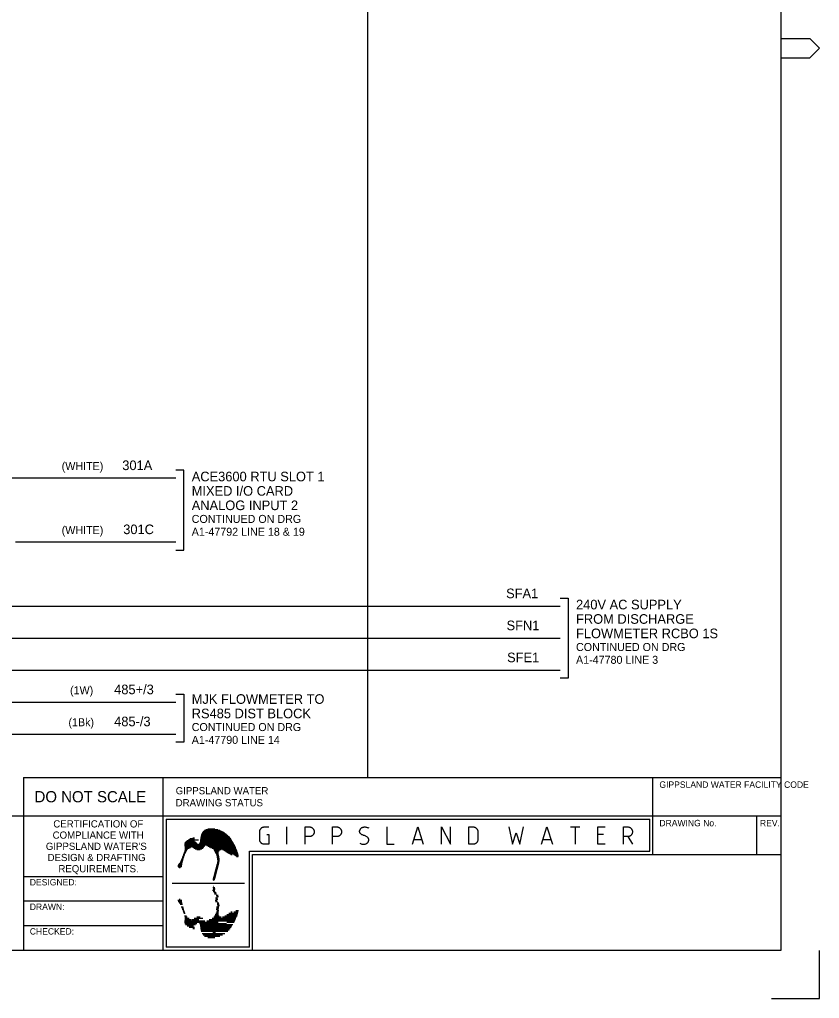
# Model space of a CAD drawing. Extents: x 0 to 841, y 0 to 594.
# Drawn here: x 591.2 to 841, y 0 to 305.7 of the extents above; entities that cross this region are included whole.
import ezdxf

# ---------------------------------------------------------------- set-up
doc = ezdxf.new("R2010")
doc.units = 0
doc.layers.add('A1BORDER', color=7, linetype='Continuous')
doc.layers.add('Level 1', color=7, linetype='Continuous')

msp = doc.modelspace()

# ---------------------------------------------------------------- linework, layer by layer
at = {"layer": 'A1BORDER'}
for p, q in [((829, 581), (829, 15)), ((829, 299.76), (838, 299.76)), ((838, 299.76), (841, 296.76)), ((838, 293.76), (841, 296.76)), ((829, 293.76), (838, 293.76)), ((592.5, 69), (592.5, 15)), ((592.5, 69), (829, 69)), ((636, 69), (636, 15)), ((789, 45), (789, 69)), ((28, 57), (829, 57)), ((637, 56), (788, 56)), ((637, 56), (637, 16)), ((788, 46), (788, 56)), ((821.5, 45), (821.5, 57)), ((648.53, 52.12), (654.64, 52.12)), ((648.74, 52.32), (654.24, 52.32)), ((649.02, 52.52), (653.76, 52.52)), ((649.39, 52.72), (653.15, 52.72)), ((650.01, 52.92), (652.2, 52.92)), ((643.04, 48.92), (646.16, 48.92)), ((643.26, 49.12), (645.9, 49.12)), ((643.54, 49.32), (645.57, 49.32)), ((643.85, 49.52), (647.09, 49.52)), ((644.18, 49.72), (645.89, 49.72)), ((644.54, 49.92), (645.36, 49.92)), ((645.37, 50.12), (645.86, 50.12)), ((647.61, 48.92), (657.8, 48.92)), ((647.63, 49.12), (657.68, 49.12)), ((647.66, 49.32), (657.57, 49.32)), ((647.69, 49.52), (657.44, 49.52)), ((647.71, 49.72), (657.31, 49.72)), ((647.75, 49.92), (657.17, 49.92)), ((647.78, 50.12), (657.02, 50.12)), ((647.81, 50.32), (656.86, 50.32)), ((647.85, 50.52), (656.69, 50.52)), ((647.88, 50.72), (656.5, 50.72)), ((647.91, 50.92), (656.3, 50.92)), ((647.96, 51.12), (656.08, 51.12)), ((648.03, 51.32), (655.85, 51.32)), ((648.12, 51.52), (655.59, 51.52)), ((648.23, 51.72), (655.31, 51.72)), ((648.37, 51.92), (655, 51.92)), ((642.72, 45.92), (643.3, 45.92)), ((642.73, 48.12), (658.25, 48.12)), ((642.74, 47.92), (658.35, 47.92)), ((642.75, 48.32), (646.79, 48.32)), ((642.79, 47.72), (649.08, 47.72)), ((642.79, 46.12), (643.4, 46.12)), ((642.81, 48.52), (646.55, 48.52)), ((642.83, 47.52), (648.95, 47.52)), ((642.84, 46.32), (643.5, 46.32)), ((642.85, 47.31), (644.88, 47.31)), ((642.87, 47.12), (644.57, 47.12)), ((642.87, 46.52), (643.6, 46.52)), ((642.88, 46.92), (644.23, 46.92)), ((642.88, 46.72), (643.83, 46.72)), ((642.9, 48.72), (646.37, 48.72)), ((645.14, 47.31), (648.83, 47.31)), ((645.49, 47.12), (648.67, 47.12)), ((645.76, 46.92), (648.42, 46.92)), ((646.05, 46.72), (648.11, 46.72)), ((646.62, 46.52), (647.67, 46.52)), ((647.19, 48.32), (658.14, 48.32)), ((647.42, 48.52), (658.03, 48.52)), ((647.54, 48.72), (657.92, 48.72)), ((649.72, 47.72), (658.45, 47.72)), ((650.12, 47.52), (658.55, 47.52)), ((650.48, 47.31), (658.64, 47.31)), ((650.87, 47.12), (658.73, 47.12)), ((651.36, 46.92), (658.82, 46.92)), ((651.76, 46.72), (658.9, 46.72)), ((651.88, 46.52), (654.15, 46.52)), ((651.99, 46.32), (653.71, 46.32)), ((652.1, 46.12), (653.52, 46.12)), ((652.2, 45.92), (653.4, 45.92)), ((654.57, 46.52), (658.99, 46.52)), ((655, 46.32), (659.07, 46.32)), ((655.31, 46.12), (659.14, 46.12)), ((655.62, 45.92), (659.22, 45.92)), ((663, 46), (788, 46)), ((663, 16), (663, 46)), ((641.55, 42.92), (642.2, 42.92)), ((641.64, 43.12), (642.25, 43.12)), ((641.73, 43.32), (642.3, 43.32)), ((641.82, 43.51), (642.35, 43.51)), ((641.91, 43.72), (642.41, 43.72)), ((641.99, 43.92), (642.48, 43.92)), ((642.06, 44.12), (642.55, 44.12)), ((642.13, 44.32), (642.62, 44.32)), ((642.21, 44.52), (642.69, 44.52)), ((642.28, 44.72), (642.76, 44.72)), ((642.35, 44.92), (642.83, 44.92)), ((642.43, 45.12), (642.9, 45.12)), ((642.5, 45.32), (643, 45.32)), ((642.57, 45.52), (643.1, 45.52)), ((642.65, 45.72), (643.2, 45.72)), ((652.31, 45.72), (653.33, 45.72)), ((652.41, 45.52), (653.31, 45.52)), ((652.5, 45.32), (653.34, 45.32)), ((652.6, 45.12), (653.38, 45.12)), ((652.69, 44.92), (653.41, 44.92)), ((652.78, 44.72), (653.44, 44.72)), ((652.83, 44.52), (653.48, 44.52)), ((652.86, 44.32), (653.53, 44.32)), ((652.89, 44.12), (653.57, 44.12)), ((652.91, 43.92), (653.62, 43.92)), ((652.94, 43.72), (653.67, 43.72)), ((652.97, 43.51), (653.71, 43.51)), ((653, 43.32), (653.69, 43.32)), ((653.02, 43.12), (653.67, 43.12)), ((653.05, 42.92), (653.64, 42.92)), ((655.93, 45.72), (659.29, 45.72)), ((656.24, 45.52), (659.35, 45.52)), ((656.55, 45.32), (659.42, 45.32)), ((656.86, 45.12), (657.74, 45.12)), ((657.17, 44.92), (657.68, 44.92)), ((657.51, 44.72), (657.54, 44.72)), ((657.91, 45.12), (659.48, 45.12)), ((658.19, 44.92), (659.54, 44.92)), ((658.47, 44.72), (659.59, 44.72)), ((658.75, 44.52), (659.58, 44.52)), ((659.02, 44.32), (659.47, 44.32)), ((664, 45), (829, 45)), ((664, 15), (664, 45)), ((640.62, 41.32), (641.88, 41.32)), ((640.63, 41.52), (641.93, 41.52)), ((640.72, 41.12), (641.73, 41.12)), ((640.73, 41.72), (641.95, 41.72)), ((640.9, 41.92), (641.97, 41.92)), ((641.03, 40.92), (641.43, 40.92)), ((641.1, 42.12), (642, 42.12)), ((641.25, 42.31), (642.04, 42.31)), ((641.37, 42.52), (642.09, 42.52)), ((641.46, 42.72), (642.15, 42.72)), ((652.3, 39.92), (652.93, 39.92)), ((652.36, 40.12), (652.99, 40.12)), ((652.41, 40.32), (653.04, 40.32)), ((652.47, 40.52), (653.1, 40.52)), ((652.52, 40.72), (653.15, 40.72)), ((652.57, 40.92), (653.2, 40.92)), ((652.63, 41.12), (653.26, 41.12)), ((652.68, 41.32), (653.31, 41.32)), ((652.74, 41.52), (653.37, 41.52)), ((652.79, 41.72), (653.41, 41.72)), ((652.85, 41.92), (653.45, 41.92)), ((652.9, 42.12), (653.49, 42.12)), ((652.95, 42.31), (653.53, 42.31)), ((652.99, 42.52), (653.57, 42.52)), ((653.03, 42.72), (653.61, 42.72)), ((636, 38), (592.5, 38)), ((651.63, 37.32), (652.23, 37.32)), ((651.64, 37.12), (652.17, 37.12)), ((651.65, 37.52), (652.28, 37.52)), ((651.71, 37.72), (652.34, 37.72)), ((651.76, 37.92), (652.39, 37.92)), ((651.79, 36.92), (651.9, 36.92)), ((651.82, 38.12), (652.44, 38.12)), ((651.87, 38.32), (652.5, 38.32)), ((651.92, 38.52), (652.55, 38.52)), ((651.98, 38.72), (652.61, 38.72)), ((652.03, 38.92), (652.66, 38.92)), ((652.09, 39.12), (652.72, 39.12)), ((652.14, 39.32), (652.77, 39.32)), ((652.2, 39.52), (652.82, 39.52)), ((652.25, 39.72), (652.88, 39.72)), ((638.93, 35.98), (661.47, 35.98)), ((651.54, 33.84), (652.17, 33.84)), ((651.63, 34.64), (652.23, 34.64)), ((651.71, 34.24), (652.34, 34.24)), ((651.79, 35.04), (651.9, 35.04)), ((640.62, 30.64), (641.88, 30.64)), ((641.03, 31.04), (641.43, 31.04)), ((651.65, 33.44), (652.28, 33.44)), ((652.03, 33.04), (652.66, 33.04)), ((652.14, 32.64), (652.77, 32.64)), ((652.34, 30.64), (652.97, 30.64)), ((652.47, 31.44), (653.1, 31.44)), ((652.57, 31.04), (653.2, 31.04)), ((652.66, 32.24), (653.29, 32.24)), ((652.77, 31.84), (653.4, 31.84)), ((636, 30.34), (592.5, 30.34)), ((640.73, 30.24), (641.95, 30.24)), ((641.1, 29.84), (642, 29.84)), ((641.37, 29.44), (642.09, 29.44)), ((641.73, 28.64), (642.3, 28.64)), ((641.91, 28.24), (642.41, 28.24)), ((642.06, 27.84), (642.55, 27.84)), ((652.45, 30.24), (653.07, 30.24)), ((652.66, 27.84), (653.35, 27.84)), ((652.72, 28.24), (653.44, 28.24)), ((652.77, 28.64), (653.46, 28.64)), ((652.9, 29.84), (653.49, 29.84)), ((652.99, 29.44), (653.57, 29.44)), ((653.05, 29.04), (653.64, 29.04)), ((642.21, 27.44), (642.69, 27.44)), ((642.35, 27.04), (642.83, 27.04)), ((642.5, 26.64), (643, 26.64)), ((642.79, 25.84), (643.4, 25.84)), ((642.85, 24.65), (644.88, 24.65)), ((642.87, 25.44), (643.6, 25.44)), ((642.88, 25.04), (644.23, 25.04)), ((645.14, 24.65), (647.18, 24.65)), ((645.76, 25.04), (648.42, 25.04)), ((646.62, 25.44), (647.67, 25.44)), ((650.48, 24.65), (658.64, 24.65)), ((651.36, 25.04), (658.82, 25.04)), ((651.88, 25.44), (654.15, 25.44)), ((652.1, 25.84), (653.52, 25.84)), ((652.31, 26.24), (653.33, 26.24)), ((652.5, 26.64), (653.34, 26.64)), ((652.69, 27.04), (653.41, 27.04)), ((652.83, 27.44), (653.48, 27.44)), ((654.57, 25.44), (658.99, 25.44)), ((655.31, 25.84), (659.14, 25.84)), ((655.93, 26.24), (659.29, 26.24)), ((656.55, 26.64), (659.42, 26.64)), ((657.17, 27.04), (657.68, 27.04)), ((658.19, 27.04), (659.54, 27.04)), ((658.75, 27.44), (659.58, 27.44)), ((636, 22.67), (592.5, 22.67)), ((642.73, 23.84), (653.27, 23.84)), ((642.79, 24.24), (649.08, 24.24)), ((642.81, 23.44), (646.55, 23.44)), ((643.04, 23.04), (646.16, 23.04)), ((643.54, 22.64), (645.57, 22.64)), ((644.18, 22.24), (645.89, 22.24)), ((645.37, 21.84), (645.86, 21.84)), ((647.42, 23.44), (655.89, 23.44)), ((647.61, 23.04), (657.8, 23.04)), ((647.66, 22.64), (657.57, 22.64)), ((647.71, 22.24), (657.31, 22.24)), ((647.78, 21.84), (657.02, 21.84)), ((647.85, 21.44), (656.69, 21.44)), ((649.72, 24.24), (658.45, 24.24)), ((655.94, 23.84), (658.25, 23.84)), ((647.91, 21.04), (656.3, 21.04)), ((648.23, 20.24), (655.31, 20.24)), ((648.53, 19.84), (654.64, 19.84)), ((649.02, 19.44), (653.76, 19.44)), ((650.01, 19.04), (652.2, 19.04)), ((651.57, 20.64), (652.44, 20.64)), ((663, 16), (637, 16)), ((829, 15), (28, 15)), ((829, 15), (829, 15)), ((841, 0), (841, 15)), ((826, 0), (841, 0))]:
    msp.add_line(p, q, dxfattribs=at)
for points in [[(668.49, 51.15), (669.06, 51.15), (669.06, 48.16), (667.64, 48.16), (667.51, 48.16), (667.39, 48.18), (667.28, 48.21), (667.15, 48.25), (667.04, 48.3), (666.93, 48.36), (666.82, 48.43), (666.73, 48.51), (666.64, 48.6), (666.55, 48.7), (666.48, 48.8), (666.41, 48.91), (666.35, 49.02), (666.31, 49.14), (666.27, 49.27), (666.24, 49.39), (666.22, 49.52), (666.22, 49.66), (666.22, 52.05), (666.22, 52.18), (666.24, 52.31), (666.27, 52.43), (666.31, 52.56), (666.35, 52.67), (666.41, 52.79), (666.48, 52.9), (666.55, 53), (666.64, 53.1), (666.73, 53.19), (666.82, 53.27), (666.93, 53.34), (667.04, 53.4), (667.15, 53.45), (667.28, 53.49), (667.39, 53.52), (667.51, 53.54), (667.64, 53.54), (669.06, 53.54)], [(674.74, 48.16), (674.74, 53.54)], [(680.42, 48.16), (680.42, 53.54), (681.84, 53.54), (681.96, 53.54), (682.08, 53.52), (682.2, 53.49), (682.32, 53.45), (682.43, 53.4), (682.54, 53.34), (682.65, 53.27), (682.74, 53.19), (682.84, 53.1), (682.92, 53), (682.99, 52.9), (683.06, 52.79), (683.12, 52.67), (683.17, 52.56), (683.21, 52.43), (683.23, 52.31), (683.25, 52.18), (683.26, 52.05), (683.25, 51.91), (683.23, 51.78), (683.21, 51.66), (683.17, 51.53), (683.12, 51.42), (683.06, 51.3), (682.99, 51.19), (682.92, 51.09), (682.84, 50.99), (682.74, 50.9), (682.65, 50.82), (682.54, 50.75), (682.43, 50.69), (682.32, 50.64), (682.2, 50.6), (682.08, 50.57), (681.96, 50.55), (681.84, 50.55), (680.42, 50.55)], [(688.93, 48.16), (688.93, 53.54), (690.35, 53.54), (690.47, 53.54), (690.59, 53.52), (690.71, 53.49), (690.83, 53.45), (690.94, 53.4), (691.05, 53.34), (691.16, 53.27), (691.26, 53.19), (691.35, 53.1), (691.43, 53), (691.51, 52.9), (691.57, 52.79), (691.63, 52.67), (691.68, 52.56), (691.72, 52.43), (691.75, 52.31), (691.76, 52.18), (691.77, 52.05), (691.76, 51.91), (691.75, 51.78), (691.72, 51.66), (691.68, 51.53), (691.63, 51.42), (691.57, 51.3), (691.51, 51.19), (691.43, 51.09), (691.35, 50.99), (691.26, 50.9), (691.16, 50.82), (691.05, 50.75), (690.94, 50.69), (690.83, 50.64), (690.71, 50.6), (690.59, 50.57), (690.47, 50.55), (690.35, 50.55), (688.93, 50.55)], [(697.45, 48.46), (697.67, 48.36), (697.9, 48.27), (698.12, 48.21), (698.36, 48.17), (698.6, 48.16), (698.84, 48.16), (698.87, 48.16), (699.03, 48.18), (699.18, 48.21), (699.33, 48.26), (699.48, 48.32), (699.62, 48.4), (699.72, 48.46), (699.81, 48.53), (699.9, 48.61), (699.98, 48.69), (700.05, 48.78), (700.11, 48.88), (700.17, 48.99), (700.22, 49.09), (700.25, 49.21), (700.28, 49.32), (700.29, 49.36), (700.3, 49.44), (700.3, 49.52), (700.3, 49.61), (700.29, 49.69), (700.27, 49.77), (700.25, 49.86), (700.22, 49.93), (700.18, 50.01), (700.14, 50.09), (700.09, 50.15), (700.04, 50.21), (700.01, 50.25), (699.85, 50.39), (699.69, 50.51), (699.52, 50.61), (699.34, 50.7), (699.15, 50.78), (698.95, 50.83), (698.87, 50.85), (698.68, 50.9), (698.49, 50.96), (698.3, 51.04), (698.12, 51.14), (697.96, 51.26), (697.8, 51.39), (697.73, 51.45), (697.67, 51.51), (697.62, 51.57), (697.58, 51.64), (697.53, 51.71), (697.5, 51.79), (697.47, 51.87), (697.46, 51.95), (697.44, 52.04), (697.43, 52.12), (697.43, 52.21), (697.44, 52.29), (697.45, 52.35), (697.47, 52.46), (697.51, 52.58), (697.55, 52.69), (697.61, 52.79), (697.67, 52.89), (697.74, 52.99), (697.82, 53.07), (697.9, 53.15), (697.99, 53.23), (698.02, 53.24), (698.15, 53.33), (698.3, 53.4), (698.44, 53.45), (698.6, 53.5), (698.75, 53.52), (698.87, 53.54), (699.11, 53.55), (699.35, 53.53), (699.58, 53.49), (699.82, 53.43), (700.04, 53.35), (700.27, 53.25)], [(705.96, 53.54), (705.96, 48.16), (708.23, 48.16)], [(713.91, 48.16), (715.61, 53.54), (717.32, 48.16)], [(722.99, 48.16), (722.99, 53.54), (725.83, 48.16), (725.83, 53.54)], [(731.52, 48.16), (731.52, 53.54), (732.94, 53.54), (733.06, 53.54), (733.18, 53.52), (733.3, 53.49), (733.42, 53.45), (733.53, 53.4), (733.64, 53.34), (733.75, 53.27), (733.84, 53.19), (733.94, 53.1), (734.02, 53), (734.09, 52.9), (734.16, 52.79), (734.22, 52.67), (734.27, 52.56), (734.31, 52.43), (734.33, 52.31), (734.35, 52.18), (734.36, 52.05), (734.36, 49.66), (734.35, 49.52), (734.33, 49.39), (734.31, 49.27), (734.27, 49.14), (734.22, 49.02), (734.16, 48.91), (734.09, 48.8), (734.02, 48.7), (733.94, 48.6), (733.84, 48.51), (733.75, 48.43), (733.64, 48.36), (733.53, 48.3), (733.42, 48.25), (733.3, 48.21), (733.18, 48.18), (733.06, 48.16), (732.94, 48.16), (731.52, 48.16)], [(744.01, 53.54), (745.14, 48.16), (746.28, 51.75), (747.41, 48.16), (748.55, 53.54)], [(754.22, 48.16), (755.92, 53.54), (757.63, 48.16)], [(763.31, 53.54), (766.15, 53.54)], [(764.73, 53.54), (764.73, 48.16)], [(774.09, 48.16), (771.82, 48.16), (771.82, 53.54), (774.09, 53.54)], [(779.78, 48.16), (779.78, 53.54), (781.2, 53.54), (781.32, 53.54), (781.44, 53.52), (781.56, 53.49), (781.68, 53.45), (781.79, 53.4), (781.9, 53.34), (782.01, 53.27), (782.1, 53.19), (782.2, 53.1), (782.28, 53), (782.35, 52.9), (782.42, 52.79), (782.48, 52.67), (782.53, 52.56), (782.56, 52.43), (782.59, 52.31), (782.61, 52.18), (782.61, 52.05), (782.61, 51.91), (782.59, 51.78), (782.56, 51.66), (782.53, 51.53), (782.48, 51.42), (782.42, 51.3), (782.35, 51.19), (782.28, 51.09), (782.2, 50.99), (782.1, 50.9), (782.01, 50.82), (781.9, 50.75), (781.79, 50.69), (781.68, 50.64), (781.56, 50.6), (781.44, 50.57), (781.32, 50.55), (781.2, 50.55), (779.78, 50.55)], [(714.48, 49.66), (716.75, 49.66)], [(754.79, 49.66), (757.06, 49.66)], [(773.53, 51.15), (771.82, 51.15)], [(781.2, 50.55), (782.61, 48.16)]]:
    msp.add_lwpolyline(points, dxfattribs=at)
at = {"layer": 'Level 1'}
for p, q in [((700, 69), (700, 572.5)), ((640, 162.5), (315, 162.5)), ((640, 142.5), (590, 142.5)), ((315, 122.5), (760, 122.5)), ((315, 112.5), (760, 112.5)), ((315, 102.5), (760, 102.5)), ((315, 92.5), (640, 92.5)), ((315, 82.5), (640, 82.5))]:
    msp.add_line(p, q, dxfattribs=at)
for points in [[(640, 140), (642.5, 140), (642.5, 165), (640, 165)], [(760, 125), (762.5, 125), (762.5, 100), (760, 100)], [(640, 95), (642.5, 95), (642.5, 80), (640, 80)]]:
    msp.add_lwpolyline(points, dxfattribs=at)

# ---------------------------------------------------------------- texts
at = {"layer": 'A1BORDER'}
for s, height, p in [('GIPPSLAND WATER FACILITY CODE', 2, (791.03, 65.77)), ('DO NOT SCALE', 3.5, (595.92, 61.25)), ('GIPPSLAND WATER', 2.25, (640, 63.75)), ('DRAWING STATUS', 2.25, (640, 60)), ('CERTIFICATION OF', 2.25, (601.79, 53.39)), ('DRAWING No.', 2, (791.03, 53.77)), ('REV.', 2, (822.43, 53.77)), ('COMPLIANCE WITH', 2.25, (601.57, 49.89)), ("GIPPSLAND WATER'S", 2.25, (599.45, 46.39)), ('DESIGN & DRAFTING', 2.25, (600, 42.89)), ('REQUIREMENTS.', 2.25, (603.37, 39.39)), ('DESIGNED:', 2, (594.44, 35.29)), ('DRAWN:', 2, (594.44, 27.62)), ('CHECKED:', 2, (594.44, 19.95))]:
    msp.add_text(s, height=height, dxfattribs=at).set_placement(p)
at = {"layer": 'Level 1'}
for s, height, p in [('(WHITE)', 2.5, (604.4, 165)), ('301A', 3, (623.32, 165)), ('ACE3600 RTU SLOT 1', 3, (645, 161.5)), ('MIXED I/O CARD', 3, (645, 157)), ('ANALOG INPUT 2', 3, (645, 152.5)), ('CONTINUED ON DRG', 2.5, (645, 148.5)), ('(WHITE)', 2.5, (604.4, 145)), ('301C', 3, (623.62, 145)), ('A1-47792 LINE 18 & 19', 2.5, (645, 144.5)), ('SFA1', 3, (743.17, 125)), ('240V AC SUPPLY', 3, (765, 121.5)), ('FROM DISCHARGE', 3, (765, 117)), ('SFN1', 3, (743.31, 115)), ('FLOWMETER RCBO 1S', 3, (765, 112.5)), ('CONTINUED ON DRG', 2.5, (765, 108.5)), ('SFE1', 3, (743.47, 105)), ('A1-47780 LINE 3', 2.5, (765, 104.5)), ('485+/3', 3, (620.78, 95)), ('(1W)', 2.5, (607.01, 95)), ('MJK FLOWMETER TO', 3, (645, 92)), ('RS485 DIST BLOCK', 3, (645, 87.5)), ('(1Bk)', 2.5, (606.51, 85)), ('485-/3', 3, (620.78, 85)), ('CONTINUED ON DRG', 2.5, (645, 83.5)), ('A1-47790 LINE 14', 2.5, (645, 79.5))]:
    msp.add_text(s, height=height, dxfattribs=at).set_placement(p)

doc.saveas('drawing.dxf')
